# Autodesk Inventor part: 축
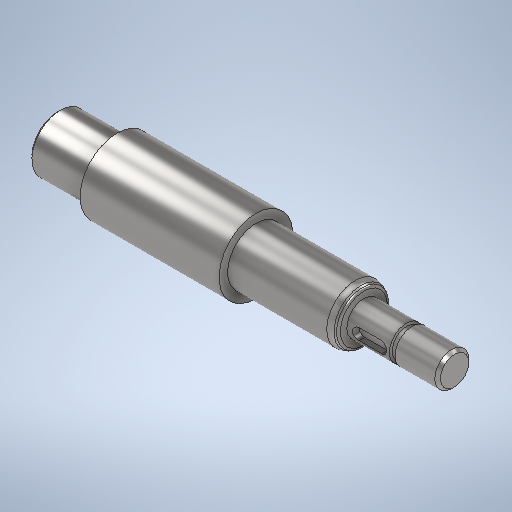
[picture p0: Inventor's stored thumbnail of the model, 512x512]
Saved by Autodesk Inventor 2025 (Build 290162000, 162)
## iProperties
Created: 2024-08
Part Number: 축
Material: 강철, 연강
Document SubType Name: Modeling
Designer: onair
Density: 7.86 g/cm^3
Appearance: 기본값
Author: jhkim
Sending System: Autodesk Inventor 2025
Preprocessor: ST-DEVELOPER v20
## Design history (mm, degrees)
feature "솔리드2"
node "솔리드1"
